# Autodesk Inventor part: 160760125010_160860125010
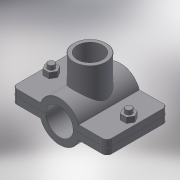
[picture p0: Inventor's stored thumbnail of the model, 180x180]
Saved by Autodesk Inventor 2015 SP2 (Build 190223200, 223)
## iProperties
Created: 2017-05
Part Number: 160760125010_160860125010
Material: Generic
Description: PLASSON SADDLE 125-1"
Document SubType Name: Modeling
Designer: KIM
Density: 1 g/cm^3
Appearance: Default
Author: KIM
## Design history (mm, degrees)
derived "16076.ipt"
feature "Solid1::16076.ipt"
feature "Solid2::16076.ipt"
tag "TaggingFeature1"
body "Solid1"
other parameters: "d0" = 137.5, "d1" = 184, "d2" = 62.5, "d3" = 125, "d4" = 124, "d5" = 0, "d6" = 9.2, "d7" = 184, "d8" = 0.1, "d10" = 0, "d11" = 1.25, "d14" = 39.3783, "d20" = 1.25, "d23" = 1.25, "d36" = 13, "d37" = 10.4, "d38" = 70.5, "d39" = 0, "d40" = 3, "d41" = 5, "d42" = 0, "d43" = 8, "d44" = 3, "d45" = 0, "d46" = 1.25, "d51" = 94, "d52" = 30.291, "d53" = 21, "d54" = 0, "d55" = 25, "d57" = 0, "d58" = 135, "d60" = 0, "d62" = 13, "d63" = 10.4, "d66" = 103.2, "d_" = 125, "B_" = 25, "G_" = 30.291, "A_" = 94, "L_" = 184, "L_1" = 124, "l_2" = 21
